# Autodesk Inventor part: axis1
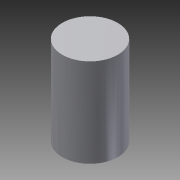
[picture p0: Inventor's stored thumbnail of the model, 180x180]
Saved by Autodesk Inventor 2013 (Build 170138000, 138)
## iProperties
Created: 2009-11
Part Number: axis1
Document SubType Name: Modeling
Designer: pokornp
Density: 1 g/cm^3
Material: Generic
Author: pokornp
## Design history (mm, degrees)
sketch "Sketch1"
  geometry: C1 r 50 at (0, 0); 1 further point
  constraints: 1 centre point, 1 coincident
  dimensions: "d0" = 100 diameter of C1
extrude "Extrusion1" new body sketch "Sketch1" distance "d1" = 160; taper "d2" = 0 deg
body "Solid1"
